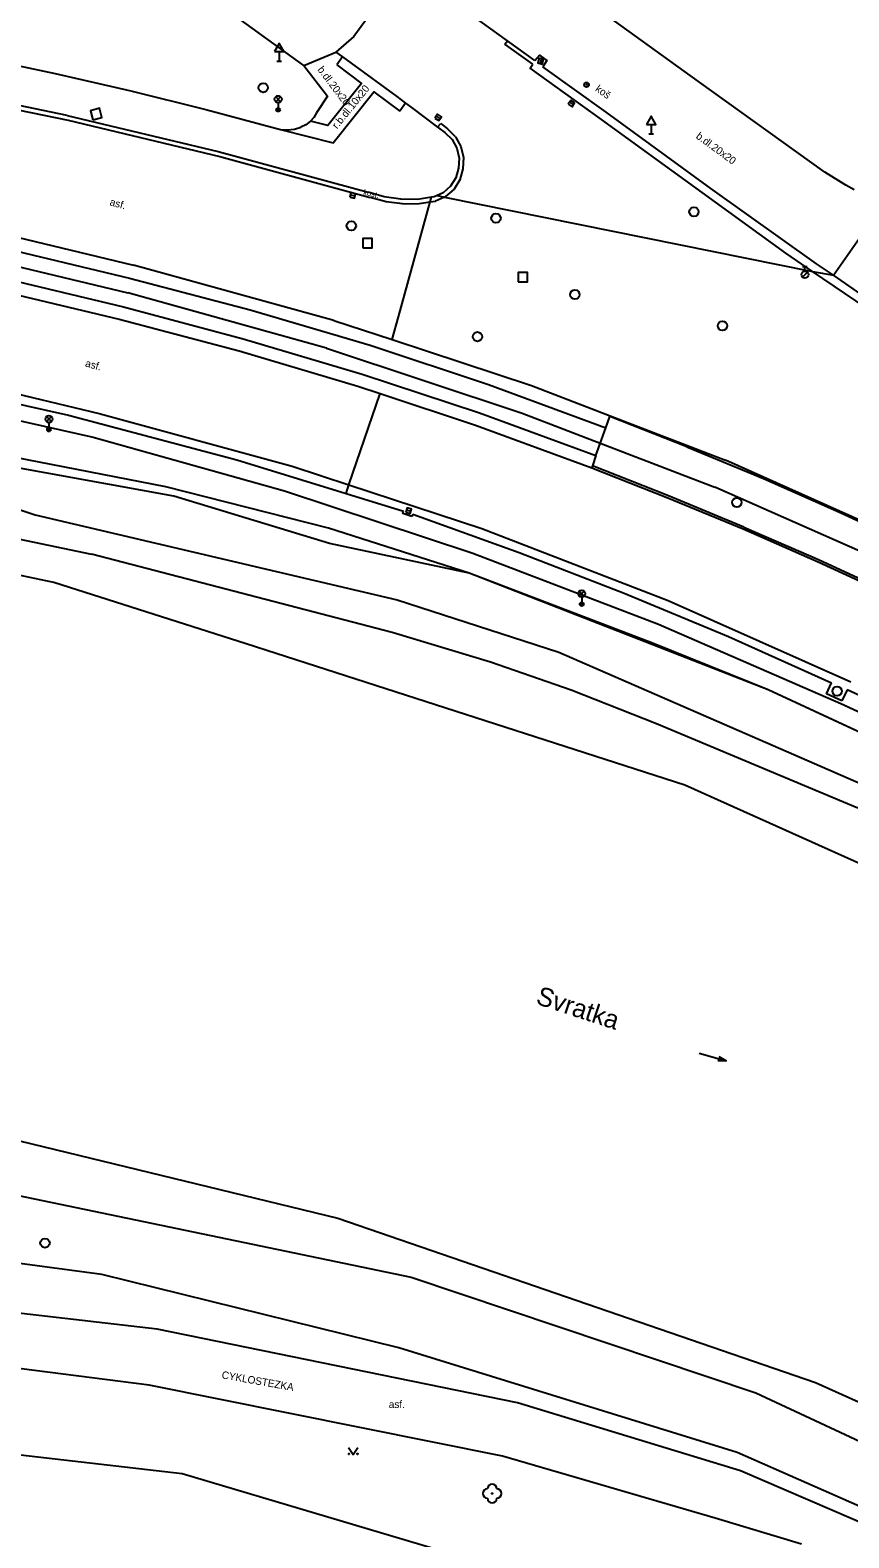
# Model space of a CAD drawing. Extents: x -599770 to -598493, y -1162076 to -1159209.
# Drawn here: x -599163.3 to -599119.5, y -1161644.3 to -1161563.7 of the extents above; entities that cross this region are included whole.
import ezdxf

# ---------------------------------------------------------------- set-up
doc = ezdxf.new("R2010")
doc.units = 0
doc.layers.add('Podklad', color=7, linetype='Continuous')

msp = doc.modelspace()

# ---------------------------------------------------------------- linework, layer by layer
at = {"layer": 'Podklad'}
for p, q in [((-599149.96, -1161564.871), (-599149.96, -1161565.38)), ((-599150.085, -1161565.38), (-599149.835, -1161565.38)), ((-599135.944, -1161565.26), (-599136.016, -1161565.5)), ((-599150.143, -1161567.55), (-599149.878, -1161567.285)), ((-599150.143, -1161567.285), (-599149.878, -1161567.55)), ((-599150.01, -1161567.605), (-599150.01, -1161567.98)), ((-599134.445, -1161567.583), (-599134.235, -1161567.717)), ((-599141.565, -1161568.323), (-599141.355, -1161568.457)), ((-599130.08, -1161568.761), (-599130.08, -1161569.27)), ((-599130.205, -1161569.27), (-599129.955, -1161569.27)), ((-599146.152, -1161572.532), (-599145.908, -1161572.588)), ((-599121.989, -1161576.926), (-599121.724, -1161576.661)), ((-599121.985, -1161576.352), (-599121.735, -1161576.352)), ((-599121.86, -1161576.602), (-599121.86, -1161576.352)), ((-599162.393, -1161584.65), (-599162.128, -1161584.385)), ((-599162.393, -1161584.385), (-599162.128, -1161584.65)), ((-599162.26, -1161584.705), (-599162.26, -1161585.08)), ((-599143.16, -1161589.374), (-599142.92, -1161589.446)), ((-599133.922, -1161593.98), (-599133.657, -1161593.715)), ((-599133.922, -1161593.715), (-599133.657, -1161593.98)), ((-599133.79, -1161594.035), (-599133.79, -1161594.41)), ((-599127.514, -1161618.413), (-599126.07, -1161618.82))]:
    msp.add_line(p, q, dxfattribs=at)
for points in [[(-599137.75, -1161564.29), (-599139.21, -1161563.25), (-599139.49, -1161563.04), (-599140.03, -1161562.64), (-599142.47, -1161560.9), (-599143.03, -1161560.49), (-599143.28, -1161560.31), (-599146.46, -1161558.01), (-599154.39, -1161552.27), (-599161.77, -1161546.92), (-599176.95, -1161535.88), (-599186.7, -1161528.83), (-599194.65, -1161523.08), (-599195.05, -1161522.79), (-599195.41, -1161522.53), (-599195.87, -1161522.2), (-599198.3, -1161520.43), (-599198.78, -1161520.08), (-599199.1, -1161519.85), (-599201.77, -1161517.89)], [(-599148.63, -1161565.61), (-599164.3, -1161554.29), (-599181.34, -1161541.97)], [(-599120.79, -1161571.31), (-599127.55, -1161566.47), (-599133.23, -1161562.37)], [(-599145.19, -1161563), (-599145.97, -1161564.06)], [(-599145.97, -1161564.06), (-599146.92, -1161564.91)], [(-599148.63, -1161565.61), (-599146.92, -1161564.91), (-599146.58, -1161565.16), (-599146.11, -1161565.49)], [(-599137.89, -1161564.47), (-599137.75, -1161564.29)], [(-599136.41, -1161565.55), (-599137.89, -1161564.47)], [(-599136.29, -1161565.35), (-599137.75, -1161564.29)], [(-599177.62, -1161565.42), (-599169.41, -1161566.86), (-599161.24, -1161568.54)], [(-599165.97, -1161565.18), (-599161.92, -1161566.04), (-599157.89, -1161566.97), (-599153.88, -1161567.97), (-599149.88, -1161569.03)], [(-599148.63, -1161565.61), (-599147.37, -1161567.26), (-599147.96, -1161568.14)], [(-599146.88, -1161565.58), (-599145.55, -1161566.57), (-599147.36, -1161568.83), (-599148.28, -1161568.59)], [(-599146.58, -1161565.16), (-599146.88, -1161565.58)], [(-599146.11, -1161565.49), (-599143.67, -1161567.28), (-599143.2, -1161567.63), (-599142.89, -1161567.86), (-599141.49, -1161568.91), (-599141.44, -1161568.95), (-599141.11, -1161569.19)], [(-599132.74, -1161568.5), (-599136.55, -1161565.76), (-599136.41, -1161565.55)], [(-599136.29, -1161565.35), (-599136.04, -1161565.07), (-599135.65, -1161565.34), (-599135.86, -1161565.68)], [(-599132.49, -1161568.11), (-599135.86, -1161565.68)], [(-599161.29, -1161568.28), (-599169.42, -1161566.6)], [(-599149.88, -1161569.03), (-599147.07, -1161569.74), (-599144.89, -1161567.02), (-599143.51, -1161568.05)], [(-599147.96, -1161568.14), (-599148.11, -1161568.39), (-599148.28, -1161568.59), (-599148.53, -1161568.78), (-599148.79, -1161568.91)], [(-599143.2, -1161567.63), (-599143.51, -1161568.05)], [(-599115.54, -1161580.16), (-599120.34, -1161576.83), (-599121.24, -1161576.21), (-599126.89, -1161572.19), (-599132.49, -1161568.11)], [(-599161.29, -1161568.28), (-599153.21, -1161570.21), (-599145.2, -1161572.38)], [(-599161.24, -1161568.54), (-599153.13, -1161570.48), (-599145.09, -1161572.67)], [(-599149.14, -1161569.02), (-599148.79, -1161568.91)], [(-599141.49, -1161568.91), (-599141.32, -1161568.71)], [(-599141.32, -1161568.71), (-599140.97, -1161569)], [(-599121.45, -1161576.62), (-599122.88, -1161575.65), (-599132.74, -1161568.5)], [(-599149.88, -1161569.03), (-599149.51, -1161569.06)], [(-599149.51, -1161569.06), (-599149.14, -1161569.02)], [(-599141.11, -1161569.19), (-599140.72, -1161569.57), (-599140.46, -1161570.04), (-599140.34, -1161570.57), (-599140.38, -1161571.11)], [(-599140.53, -1161569.42), (-599140.97, -1161569)], [(-599140.53, -1161569.42), (-599140.24, -1161569.94), (-599140.1, -1161570.53), (-599140.14, -1161571.14)], [(-599194.71, -1161570.27), (-599185.37, -1161571.08), (-599176.07, -1161572.36), (-599166.86, -1161574.09), (-599157.74, -1161576.29)], [(-599194.76, -1161570.97), (-599185.46, -1161571.79), (-599176.21, -1161573.07), (-599167.03, -1161574.8), (-599157.95, -1161576.98)], [(-599140.38, -1161571.11), (-599140.52, -1161571.62), (-599140.8, -1161572.07), (-599141.19, -1161572.42), (-599141.52, -1161572.57), (-599141.67, -1161572.64)], [(-599140.14, -1161571.14), (-599140.3, -1161571.72), (-599140.61, -1161572.22), (-599141.06, -1161572.62), (-599141.12, -1161572.65)], [(-599119.67, -1161572.01), (-599120.79, -1161571.31)], [(-599119.23, -1161572.26), (-599119.67, -1161572.01)], [(-599196.13, -1161572.48), (-599195.43, -1161572.54), (-599186.56, -1161573.26), (-599177.05, -1161574.53), (-599167.61, -1161576.28), (-599158.28, -1161578.52)], [(-599141.67, -1161572.64), (-599141.82, -1161572.66), (-599142.56, -1161572.77), (-599143.45, -1161572.76), (-599144.34, -1161572.63), (-599145.2, -1161572.38)], [(-599143.36, -1161573.01), (-599144.24, -1161572.9), (-599145.09, -1161572.67)], [(-599143.92, -1161580.27), (-599143.584, -1161579.058), (-599141.89, -1161572.91)], [(-599143.36, -1161573.01), (-599142.48, -1161573)], [(-599142.48, -1161573), (-599141.89, -1161572.91)], [(-599141.89, -1161572.91), (-599141.82, -1161572.66)], [(-599141.89, -1161572.91), (-599141.6, -1161572.87)], [(-599141.12, -1161572.65), (-599141.6, -1161572.87)], [(-599141.52, -1161572.57), (-599141.12, -1161572.65)], [(-599141.12, -1161572.65), (-599121.45, -1161576.62)], [(-599196.16, -1161573.17), (-599186.64, -1161573.95), (-599177.18, -1161575.22), (-599167.79, -1161576.96), (-599158.5, -1161579.18)], [(-599178.09, -1161573.53), (-599168.02, -1161575.38), (-599158.05, -1161577.76)], [(-599120.34, -1161576.83), (-599117.97, -1161573.44)], [(-599157.95, -1161576.98), (-599151.5, -1161578.67), (-599145.1, -1161580.57), (-599138.77, -1161582.67), (-599132.5, -1161584.98)], [(-599147.03, -1161579.24), (-599157.74, -1161576.29)], [(-599121.45, -1161576.62), (-599120.34, -1161576.83)], [(-599092.03, -1161595.22), (-599102.51, -1161589.02), (-599112.8, -1161582.49), (-599121.45, -1161576.62)], [(-599147.43, -1161580.73), (-599158.05, -1161577.76)], [(-599158.28, -1161578.52), (-599151.88, -1161580.22), (-599145.53, -1161582.11), (-599139.25, -1161584.19), (-599133.03, -1161586.46)], [(-599158.5, -1161579.18), (-599152.09, -1161580.87)], [(-599147.03, -1161579.24), (-599143.92, -1161580.27), (-599136.47, -1161582.72), (-599132.27, -1161584.34), (-599126.11, -1161586.72)], [(-599182.56, -1161579.73), (-599174.84, -1161580.9), (-599167.17, -1161582.4), (-599159.57, -1161584.21)], [(-599179.46, -1161580.63), (-599172.02, -1161581.97), (-599170.3, -1161582.28), (-599161.21, -1161584.31), (-599152.21, -1161586.69), (-599146.38, -1161588.49), (-599143.31, -1161589.44)], [(-599152.09, -1161580.87), (-599145.75, -1161582.75), (-599144.56, -1161583.15), (-599139.46, -1161584.84)], [(-599147.43, -1161580.73), (-599136.97, -1161584.2), (-599126.68, -1161588.16)], [(-599146.23, -1161588.03), (-599144.56, -1161583.15)], [(-599046.81, -1161634.84), (-599057.69, -1161629.79), (-599077.21, -1161621.52), (-599107.62, -1161606.51), (-599123.82, -1161598.98), (-599130.01, -1161596.49), (-599139.8, -1161592.75), (-599147.32, -1161590.34), (-599156.02, -1161588.13), (-599168.93, -1161585.63), (-599175.32, -1161584.75), (-599179.38, -1161584.08), (-599180.25, -1161583.92)], [(-599180.25, -1161583.92), (-599163, -1161589.64), (-599143.65, -1161594.17), (-599135.02, -1161596.97), (-599114.73, -1161605.82), (-599080.75, -1161621.2), (-599065.94, -1161628.12), (-598998.09, -1161660.51), (-598974.99, -1161672.34), (-598953.07, -1161685.05), (-598929.76, -1161698.95), (-598888.91, -1161727.38), (-598861.19, -1161748.52), (-598845.68, -1161761.08), (-598825.16, -1161781.28), (-598808.06, -1161799.42), (-598788.14, -1161822.37), (-598730.99, -1161888.48), (-598729.85, -1161889.88)], [(-599180.25, -1161583.92), (-599163, -1161589.64), (-599143.65, -1161594.17), (-599135.02, -1161596.97), (-599114.73, -1161605.82), (-599080.75, -1161621.2), (-599065.94, -1161628.12), (-598998.09, -1161660.51), (-598974.99, -1161672.34), (-598953.07, -1161685.05), (-598929.76, -1161698.95), (-598888.91, -1161727.38), (-598861.19, -1161748.52), (-598845.68, -1161761.08), (-598825.16, -1161781.28), (-598808.06, -1161799.42), (-598788.14, -1161822.37), (-598730.99, -1161888.48), (-598729.85, -1161889.88)], [(-599167.05, -1161583.87), (-599159.9, -1161585.48)], [(-599159.57, -1161584.21), (-599149.27, -1161587.03), (-599146.23, -1161588.03), (-599139.13, -1161590.37), (-599129.17, -1161594.22), (-599119.41, -1161598.56)], [(-599139.46, -1161584.84), (-599133.24, -1161587.12)], [(-599133.03, -1161586.46), (-599132.5, -1161584.98), (-599132.29, -1161584.38), (-599132.27, -1161584.34)], [(-599128.17, -1161586), (-599132.29, -1161584.38)], [(-598799.44, -1161805.85), (-598802.25, -1161802.78), (-598809.5, -1161794.72), (-598819.13, -1161784.01), (-598839.67, -1161763.81), (-598854.43, -1161750.62), (-598875.37, -1161733.68), (-598894.03, -1161720.2), (-598928.44, -1161696.82), (-598960.02, -1161677.8), (-598988.42, -1161662.64), (-599021.49, -1161646.68), (-599046.81, -1161634.84), (-599071.35, -1161623.36), (-599123.82, -1161598.98), (-599139.8, -1161592.75), (-599147.26, -1161591.17), (-599155.59, -1161588.64), (-599172.59, -1161585.56), (-599172.49, -1161585.13)], [(-599159.9, -1161585.48), (-599149.68, -1161588.35), (-599139.6, -1161591.69)], [(-599133.03, -1161586.46), (-599133.21, -1161587.02), (-599133.24, -1161587.12)], [(-599128.17, -1161586), (-599124.08, -1161587.7), (-599120.02, -1161589.49), (-599116, -1161591.35)], [(-599115.96, -1161591.25), (-599126.11, -1161586.72)], [(-599133.24, -1161587.12), (-599129.18, -1161588.72), (-599125.16, -1161590.39), (-599121.16, -1161592.14), (-599117.2, -1161593.96)], [(-599129.15, -1161588.61), (-599133.21, -1161587.02)], [(-599146.38, -1161588.49), (-599146.23, -1161588.03)], [(-599116.59, -1161592.61), (-599126.68, -1161588.16)], [(-599162, -1161593.26), (-599165.4, -1161592.53), (-599175.55, -1161590.84), (-599180.48, -1161590.08), (-599187.09, -1161589.29), (-599189.7, -1161589.05)], [(-599176.1, -1161588.77), (-599166.56, -1161590.36), (-599159.99, -1161591.74)], [(-599125.12, -1161590.29), (-599129.15, -1161588.61)], [(-599142.87, -1161589.72), (-599143.34, -1161589.57), (-599143.31, -1161589.44)], [(-599142.82, -1161589.6), (-599142.87, -1161589.72)], [(-599142.82, -1161589.6), (-599137.14, -1161591.64), (-599131.52, -1161593.82), (-599125.95, -1161596.14), (-599120.45, -1161598.61)], [(-599125.12, -1161590.29), (-599121.13, -1161592.03), (-599117.17, -1161593.85)], [(-599143.92, -1161595.93), (-599159.99, -1161591.74)], [(-599139.6, -1161591.69), (-599129.68, -1161595.48), (-599119.94, -1161599.72)], [(-598930.62, -1161703.45), (-598962.96, -1161683.9), (-598992.16, -1161668.11), (-599026.86, -1161651.42), (-599073.57, -1161629.03), (-599101.81, -1161615.97), (-599128.28, -1161604.09), (-599151.72, -1161596.53), (-599162, -1161593.26)], [(-599138.67, -1161597.51), (-599143.92, -1161595.93)], [(-599134.36, -1161599), (-599138.67, -1161597.51)], [(-599120.71, -1161599.2), (-599120.45, -1161598.61)], [(-599129.79, -1161600.81), (-599134.36, -1161599)], [(-599119.89, -1161599.58), (-599120.71, -1161599.2)], [(-599119.6, -1161598.99), (-599119.89, -1161599.58)], [(-599077.94, -1161618.34), (-599098.57, -1161608.68), (-599119.6, -1161598.99)], [(-599119.94, -1161599.72), (-599098.94, -1161609.4), (-599078.3, -1161619.08), (-599058.56, -1161628.42), (-599038.42, -1161638)], [(-599119.04, -1161605.32), (-599129.79, -1161600.81)], [(-599126.46, -1161618.59), (-599126.07, -1161618.82), (-599126.523, -1161618.812)], [(-599170.75, -1161621.43), (-599146.82, -1161627.23), (-599121.3, -1161636.02), (-599095.23, -1161647.74), (-599059.74, -1161664.6), (-599007.25, -1161689.24), (-598975.2, -1161706.93), (-598921.73, -1161740.47), (-598888.91, -1161764.54), (-598868.49, -1161781.76), (-598847.28, -1161801.66), (-598821.59, -1161828.17), (-598818.85, -1161831.09), (-598788.93, -1161865.71), (-598745.82, -1161911.74), (-598735.07, -1161923.83)], [(-599171.53, -1161624.43), (-599142.9, -1161630.38), (-599124.48, -1161636.57), (-599045.35, -1161673.48), (-599008.75, -1161690.39), (-598974.54, -1161708.96), (-598925.65, -1161740.07), (-598887.55, -1161768.09), (-598865.96, -1161786.27), (-598821.99, -1161832.07), (-598791.69, -1161867.26)], [(-598737.79, -1161926.34), (-598791.69, -1161867.26), (-598813.1, -1161843.8), (-598846.83, -1161807.87), (-598870.15, -1161785.99), (-598909.01, -1161754.64), (-598931.6, -1161739.49), (-598949.1, -1161727.7), (-598989, -1161703.94), (-599013.81, -1161691.24), (-599043.52, -1161676.98), (-599103.15, -1161649.6), (-599125.48, -1161639.76), (-599143.56, -1161634.16), (-599159.43, -1161630.25), (-599171.54, -1161628.63), (-599185.25, -1161627.69)], [(-598939.12, -1161737.32), (-598971.25, -1161716.06), (-598991.08, -1161704.02), (-599011.56, -1161693.58), (-599055.43, -1161673.02), (-599118.11, -1161643.83), (-599125.31, -1161640.74), (-599137.22, -1161637.1), (-599156.47, -1161633.16), (-599171.45, -1161631.43), (-599176.45, -1161631.34), (-599178.96, -1161631.28)], [(-599122.04, -1161644.65), (-599126.65, -1161643.26), (-599138.02, -1161639.96), (-599156.91, -1161636.16), (-599171.54, -1161634.28), (-599178.8, -1161634.06)], [(-599184.33, -1161637.83), (-599177.67, -1161638.27), (-599155.14, -1161640.88), (-599124, -1161650.15)], [(-599146.25, -1161639.485), (-599146, -1161639.86), (-599145.75, -1161639.485)]]:
    msp.add_lwpolyline(points, dxfattribs=at)
for points in [[(-599150.21, -1161564.871), (-599149.71, -1161564.871), (-599149.96, -1161564.438)], [(-599136.064, -1161565.224), (-599136.136, -1161565.464), (-599135.896, -1161565.536), (-599135.824, -1161565.296)], [(-599159.906, -1161568.516), (-599159.424, -1161568.386), (-599159.554, -1161567.904), (-599160.036, -1161568.034)], [(-599134.513, -1161567.688), (-599134.302, -1161567.823), (-599134.167, -1161567.612), (-599134.378, -1161567.477)], [(-599141.633, -1161568.428), (-599141.422, -1161568.563), (-599141.287, -1161568.352), (-599141.498, -1161568.217)], [(-599130.33, -1161568.761), (-599129.83, -1161568.761), (-599130.08, -1161568.328)], [(-599146.18, -1161572.654), (-599145.936, -1161572.71), (-599145.88, -1161572.466), (-599146.124, -1161572.41)], [(-599145.49, -1161575.36), (-599144.99, -1161575.36), (-599144.99, -1161574.86), (-599145.49, -1161574.86)], [(-599137.19, -1161577.18), (-599136.69, -1161577.18), (-599136.69, -1161576.68), (-599137.19, -1161576.68)], [(-599143.196, -1161589.494), (-599142.956, -1161589.566), (-599142.884, -1161589.326), (-599143.124, -1161589.254)]]:
    msp.add_lwpolyline(points, close=True, dxfattribs=at)
for centre, radius in [((-599150.81, -1161566.8), 0.25), ((-599133.53, -1161566.64), 0.125), ((-599150.01, -1161567.418), 0.188), ((-599133.53, -1161566.64), 0.0152), ((-599150.01, -1161567.98), 0.1), ((-599150.01, -1161567.98), 0.0723), ((-599150.01, -1161567.98), 0.0438), ((-599138.37, -1161573.78), 0.25), ((-599127.79, -1161573.43), 0.25), ((-599146.1, -1161574.18), 0.25), ((-599121.86, -1161576.79), 0.188), ((-599134.15, -1161577.86), 0.25), ((-599126.27, -1161579.53), 0.25), ((-599139.36, -1161580.11), 0.25), ((-599162.26, -1161584.517), 0.188), ((-599162.26, -1161585.08), 0.1), ((-599162.26, -1161585.08), 0.0723), ((-599162.26, -1161585.08), 0.0438), ((-599125.5, -1161588.97), 0.25), ((-599133.79, -1161593.847), 0.188), ((-599133.79, -1161594.41), 0.1), ((-599133.79, -1161594.41), 0.0723), ((-599133.79, -1161594.41), 0.0438), ((-599120.14, -1161599.06), 0.25), ((-599162.47, -1161628.56), 0.25), ((-599146.225, -1161639.835), 0.025), ((-599145.775, -1161639.835), 0.025), ((-599138.58, -1161641.95), 0.025)]:
    msp.add_circle(centre, radius, dxfattribs=at)
for centre, start, end in [((-599138.58, -1161641.7), 0, 180), ((-599138.83, -1161641.95), 90, 270), ((-599138.58, -1161642.2), 180, 0), ((-599138.33, -1161641.95), 270, 90)]:
    msp.add_arc(centre, 0.25, start, end, dxfattribs=at)

# ---------------------------------------------------------------- texts
for s, height, rotation, p in [('b.dl.20x20', 0.4, 307, (-599147.93, -1161565.84)), ('r.b.dl.10x20', 0.4, 51, (-599146.86, -1161569.03)), ('koš', 0.4, 325.24106, (-599133.1, -1161566.95)), ('b.dl.20x20', 0.4, 323.71279, (-599127.72, -1161569.47)), ('asf.', 0.4, 344.9, (-599159.04, -1161573.08)), ('kost.', 0.3, 347.10485, (-599145.48, -1161572.52)), ('asf.', 0.4, 344.9, (-599160.35, -1161581.7)), ('Svratka', 1, 341.86, (-599136.29, -1161615.76)), ('CYKLOSTEZKA', 0.4, 349.96, (-599153.05, -1161635.79))]:
    msp.add_text(s, height=height, rotation=rotation, dxfattribs=at).set_placement(p)
msp.add_text('asf.', height=0.4, dxfattribs=at).set_placement((-599144.1, -1161637.38))

doc.saveas('drawing.dxf')
